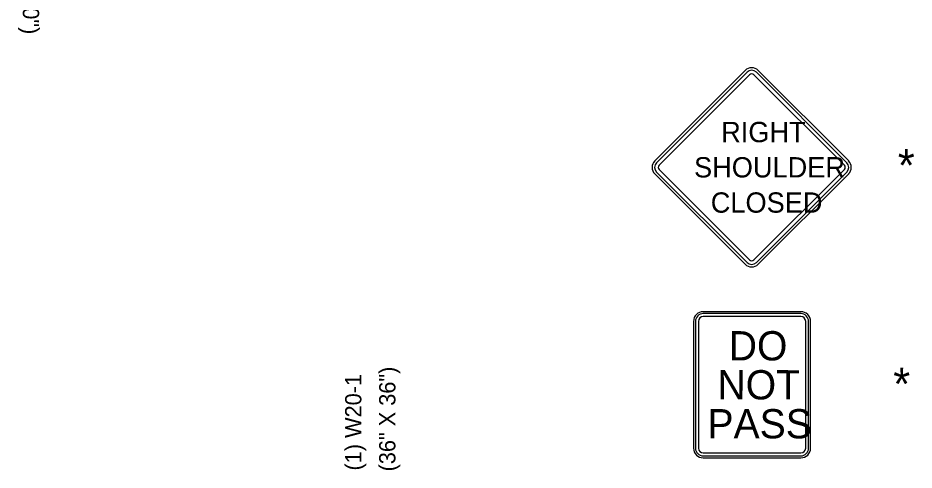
# Model space of a CAD drawing. Extents: x 1927831 to 1930787, y 596452 to 597699.
# Drawn here: x 1928492.8 to 1928823.6, y 597193.2 to 597360.2 of the extents above; entities that cross this region are included whole.
import ezdxf

# ---------------------------------------------------------------- set-up
doc = ezdxf.new("R2010")
doc.units = 0
for name, color, linetype in [('Default', 7, 'Continuous'), ('P_TC_Signs_Permanent', 7, 'Continuous'), ('P_TC_Signs_Temporary', 7, 'Continuous'), ('R_Annotation', 7, 'Continuous'), ('R_Border', 7, 'Continuous')]:
    doc.layers.add(name, color=color, linetype=linetype)

msp = doc.modelspace()

# ---------------------------------------------------------------- linework, layer by layer
at = {"layer": 'P_TC_Signs_Permanent'}
for p, q in [((1928781.78, 597251.74), (1928745.78, 597251.74)), ((1928781.78, 597251.02), (1928745.78, 597251.02)), ((1928781.78, 597249.94), (1928745.78, 597249.94)), ((1928742.18, 597248.14), (1928742.18, 597201.34)), ((1928742.9, 597248.14), (1928742.9, 597201.34)), ((1928743.98, 597248.14), (1928743.98, 597201.34)), ((1928783.58, 597201.34), (1928783.58, 597248.14)), ((1928784.66, 597201.34), (1928784.66, 597248.14)), ((1928785.38, 597201.34), (1928785.38, 597248.14)), ((1928745.78, 597199.54), (1928781.78, 597199.54)), ((1928745.78, 597198.46), (1928781.78, 597198.46)), ((1928745.78, 597197.74), (1928781.78, 597197.74))]:
    msp.add_line(p, q, dxfattribs=at)
for centre, radius, start, end in [((1928745.78, 597248.14), 3.6, 90, 180), ((1928745.78, 597248.14), 2.88, 90, 180), ((1928745.78, 597248.14), 1.8, 90, 180), ((1928781.78, 597248.14), 3.6, 360, 90), ((1928781.78, 597248.14), 2.88, 360, 90), ((1928781.78, 597248.14), 1.8, 360, 90), ((1928745.78, 597201.34), 3.6, 180, 270), ((1928745.78, 597201.34), 2.88, 180, 270), ((1928745.78, 597201.34), 1.8, 180, 270), ((1928781.78, 597201.34), 3.6, 270, 360), ((1928781.78, 597201.34), 2.88, 270, 360), ((1928781.78, 597201.34), 1.8, 270, 360)]:
    msp.add_arc(centre, radius, start, end, dxfattribs=at)
at = {"layer": 'P_TC_Signs_Temporary'}
for p, q in [((1928727.86, 597307.43), (1928761.27, 597340.84)), ((1928728.52, 597306.77), (1928761.93, 597340.18)), ((1928729.45, 597305.84), (1928762.86, 597339.25)), ((1928764.45, 597339.25), (1928797.86, 597305.84)), ((1928765.38, 597340.18), (1928798.79, 597306.77)), ((1928766.04, 597340.84), (1928799.45, 597307.43)), ((1928761.27, 597269.25), (1928727.86, 597302.66)), ((1928761.93, 597269.91), (1928728.52, 597303.32)), ((1928762.86, 597270.84), (1928729.45, 597304.25)), ((1928797.86, 597304.25), (1928764.45, 597270.84)), ((1928798.79, 597303.32), (1928765.38, 597269.91)), ((1928799.45, 597302.66), (1928766.04, 597269.25))]:
    msp.add_line(p, q, dxfattribs=at)
for centre, radius, start, end in [((1928763.65, 597338.45), 3.38, 45, 135), ((1928763.65, 597338.45), 2.44, 45, 135), ((1928763.65, 597338.45), 1.13, 45, 135), ((1928730.24, 597305.04), 3.37, 135, 225), ((1928730.24, 597305.04), 2.44, 135, 225), ((1928730.24, 597305.04), 1.12, 135, 225), ((1928797.06, 597305.04), 1.12, 315, 45), ((1928797.06, 597305.04), 2.44, 315, 45), ((1928797.06, 597305.04), 3.37, 315, 45), ((1928763.65, 597271.63), 3.38, 225, 315), ((1928763.65, 597271.63), 2.44, 225, 315), ((1928763.65, 597271.63), 1.13, 225, 315)]:
    msp.add_arc(centre, radius, start, end, dxfattribs=at)

# ---------------------------------------------------------------- texts
at = {"layer": 'Default'}
for s, p in [('(36" X 36")', (1928632.12, 597192.73)), ('(1) W20-1', (1928619.55, 597193.06))]:
    msp.add_text(s, height=6, rotation=90, dxfattribs=at).set_placement(p)
at = {"layer": 'P_TC_Signs_Permanent'}
for s, rotation, p in [('DO', 360, (1928755.17, 597233.74)), ('NOT', 359.9596, (1928751, 597219.35)), ('PASS', 360, (1928747.33, 597204.94))]:
    msp.add_text(s, height=10.8, rotation=rotation, dxfattribs=at).set_placement(p)
at = {"layer": 'P_TC_Signs_Temporary'}
for s, p in [('RIGHT', (1928752.38, 597314.34)), ('SHOULDER', (1928742.36, 597301.32)), ('CLOSED', (1928748.54, 597288.3))]:
    msp.add_text(s, height=7.5, rotation=360, dxfattribs=at).set_placement(p)
at = {"layer": 'R_Annotation'}
msp.add_text('(30" x 30")', height=5.9996, rotation=270, dxfattribs=at).set_placement((1928494.57, 597391.54))
at = {"layer": 'R_Border'}
for p in [(1928817.6, 597299.8), (1928815.91, 597219.05)]:
    msp.add_text('*', height=12, rotation=360, dxfattribs=at).set_placement(p)

doc.saveas('drawing.dxf')
